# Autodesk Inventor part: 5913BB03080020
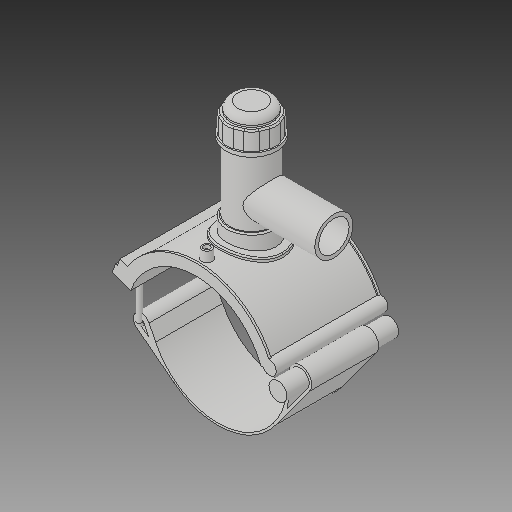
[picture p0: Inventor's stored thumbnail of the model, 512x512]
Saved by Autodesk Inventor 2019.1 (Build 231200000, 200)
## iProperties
Created: 2017-07
Part Number: 5913BB03080020
Material: Generic
Description: PLASSON HIGH VOLUME TAPPING TEE 8''IPS x 2''IPS
Document SubType Name: Modeling
Designer: KIM
Mass: 1712.7 g
Surface Area: 2671.49 cm^2
Volume: 1712.7 cm^3
Density: 1 g/cm^3
Appearance: Default
Author: KIM
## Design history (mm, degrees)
derived "5913B.ipt"
feature "Solid1::5913B.ipt"
feature "Solid2::5913B.ipt"
feature "Solid4::5913B.ipt"
feature "Solid5::5913B.ipt"
tag "TaggingFeature1"
body "Solid1"
body "Solid2"
other parameters: "d0" = 218.7, "d2" = 449.58, "d3" = 54.675, "d4" = 176.022, "d5" = 0, "d6" = 0.1, "d8" = 0, "d40" = 129.64536, "d41" = 98.415, "d43" = 0, "d45" = 0, "d47" = 230.2722, "d78" = 139.35, "d79" = 15, "d80" = 70.4088, "d82" = 5 deg, "d84" = 4, "d85" = 14, "d86" = 0, "d87" = 3, "d88" = 0, "d96" = 254.30436, "d97" = 3.52044, "d98" = 0, "d102" = 2.187, "d120" = 140 deg, "d121" = 24.228, "d122" = 20 deg, "d123" = 623.295, "d124" = 149.5908, "d126" = 0, "d153" = 176.022, "d154" = 0, "d159" = 6.1236, "d162" = 105.6132, "d163" = 0, "d164" = 109.35, "d169" = 4.0905, "d170" = 9.1854, "d172" = 0, "d173" = 1, "d175" = 109.35, "d176" = 20 deg, "d177" = 15.309, "d178" = 30.618, "d180" = 0, "d183" = 12.2472, "d184" = 12.2472, "d187" = 124.659, "d188" = 9.1854, "d189" = 15.309, "d190" = 0, "d191" = 186.9885, "d193" = 7.8732, "d194" = 3.9366, "d195" = 90 deg, "d197" = 0, "d199" = 0, "d200" = 15.309, "d202" = 0, "d203" = 194.818, "d204" = 76.66528, "d205" = 56.49021, "d206" = 68.59526, "d207" = 146.1135, "d208" = 151.95804, "d209" = 181.18074, "d210" = 69.40226, "d211" = 80.7003, "d212" = 64.56024, "d213" = 40.392, "d216" = 0, "d217" = 21.87, "d218" = 10.935, "d219" = 2.187, "d222" = 218.7, "d224" = 0, "d230" = 2.187, "d257" = 184.28, "d258" = 129.794, "d259" = 48.08, "d260" = 60.1, "d263" = 179.832, "d265" = 0, "d267" = 13.00006, "d268" = 2.60001, "d269" = 2.60001, "d271" = 2.60001, "d273" = 0, "d274" = 23.56194, "d275" = 174.96, "d277" = 87.48, "d278" = 349.92, "d280" = 0, "d281" = 218.7, "d283" = 0, "d285" = 0, "d290" = 21.87, "d291" = 28.431, "d293" = 120.285, "d294" = 112.6305, "d296" = 32.805, "d297" = 26.244, "d_" = 218.7, "B_" = 179.832, "L_" = 176.022, "d_t" = 6, "H_2" = 194.818, "H_1" = 74.93, "d_1" = 60.1, "H_" = 129.794, "d1" = 249.318, "d192" = 7.8732
